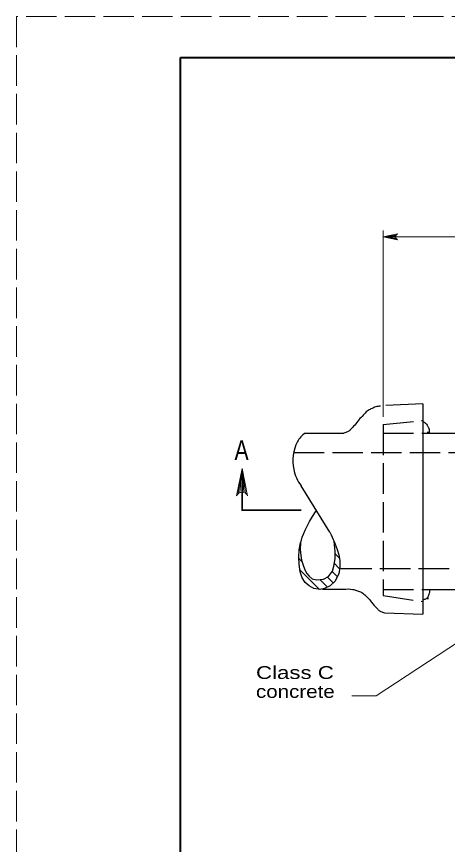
# Model space of a CAD drawing. Extents: x 1083.1 to 1117.1, y 719.4 to 741.4.
# Drawn here: x 1083.13 to 1088.38, y 731.26 to 741.35 of the extents above; entities that cross this region are included whole.
import ezdxf
from ezdxf.enums import TextEntityAlignment as Align

# ---------------------------------------------------------------- set-up
doc = ezdxf.new("R2010")
doc.units = 0
doc.header["$LTSCALE"] = 0.062
doc.linetypes.add('LONG_DASHED', pattern=[7.5, 6, -1.5])
doc.layers.add('1', color=7, linetype='Continuous', lineweight=13)

msp = doc.modelspace()

# ---------------------------------------------------------------- linework, layer by layer
at = {"layer": '1', "lineweight": 25}
for p, q in [((1085.12642, 740.85408), (1116.62642, 740.85408)), ((1088.08092, 736.63083), (1087.63217, 736.61167)), ((1088.08092, 736.63083), (1088.08092, 734.06592)), ((1086.64692, 736.27608), (1087.08667, 736.27608)), ((1087.08667, 736.27608), (1087.11675, 736.27608)), ((1088.08092, 736.27608), (1088.70717, 736.27608)), ((1086.94692, 735.0665), (1086.59733, 735.63325)), ((1086.85717, 734.37325), (1087.08667, 734.37325)), ((1087.08667, 734.37325), (1087.11675, 734.37325)), ((1088.08092, 734.36742), (1088.72042, 734.36742)), ((1087.61542, 734.08575), (1088.08092, 734.06592))]:
    msp.add_line(p, q, dxfattribs=at)
at = {"layer": '1'}
for p, q in [((1087.59625, 738.74692), (1087.59625, 736.47533)), ((1087.75742, 738.69033), (1087.59625, 738.66783)), ((1087.75192, 738.67917), (1087.59625, 738.66783)), ((1087.59625, 738.66783), (1094.52958, 738.66783)), ((1087.75025, 738.66783), (1087.59625, 738.66783)), ((1087.75317, 738.65333), (1087.59625, 738.66783)), ((1087.75933, 738.64292), (1087.59625, 738.66783)), ((1085.83083, 735.53767), (1085.87792, 735.84575)), ((1085.85058, 735.54933), (1085.87792, 735.84575)), ((1085.87792, 735.55475), (1085.87792, 735.84575)), ((1085.89942, 735.55158), (1085.87792, 735.84575)), ((1085.9205, 735.54125), (1085.87792, 735.84575)), ((1087.00217, 734.94825), (1087.0005, 734.94983)), ((1087.00825, 734.9325), (1087.00158, 734.93933)), ((1086.587, 734.85367), (1086.57717, 734.8635)), ((1086.58683, 734.85742), (1086.57775, 734.86667)), ((1086.58967, 734.90692), (1086.58617, 734.91042)), ((1086.60825, 734.707), (1086.5695, 734.74567)), ((1087.06417, 734.75092), (1087.01175, 734.8035)), ((1087.06708, 734.62242), (1087.002, 734.68775)), ((1086.8195, 734.36942), (1086.58083, 734.60892)), ((1086.98917, 734.44983), (1086.91883, 734.52042)), ((1087.03858, 734.52567), (1086.97658, 734.588)), ((1086.91725, 734.3965), (1086.82442, 734.48983))]:
    msp.add_line(p, q, dxfattribs=at)
at = {"layer": '1', "linetype": 'LONG_DASHED', "lineweight": 25}
for p, q in [((1087.59625, 736.379), (1088.08092, 736.43042)), ((1087.59625, 736.379), (1087.59625, 734.29408)), ((1087.59625, 736.27608), (1088.08092, 736.27608)), ((1086.50708, 736.03933), (1090.24283, 736.03933)), ((1087.08633, 734.62317), (1090.24283, 734.62317)), ((1087.59625, 734.36742), (1088.08092, 734.36742)), ((1087.59625, 734.29408), (1088.08092, 734.22375))]:
    msp.add_line(p, q, dxfattribs=at)
at = {"layer": '1', "linetype": 'LONG_DASHED'}
msp.add_line((1087.06867, 734.62317), (1087.08667, 734.62317), dxfattribs=at)
msp.add_lwpolyline([(1083.12642, 719.35408), (1117.12642, 719.35408), (1117.12642, 741.35408), (1083.12642, 741.35408)], close=True, dxfattribs=at)
at = {"layer": '1', "lineweight": 25}
for points in [[(1116.62642, 719.85408), (1085.12642, 719.85408), (1085.12642, 740.85408)], [(1087.00008, 734.9535), (1087.03817, 734.85558), (1087.057, 734.79183), (1087.06908, 734.72342), (1087.06867, 734.63167), (1087.05642, 734.562), (1087.01208, 734.47133), (1086.95183, 734.41475), (1086.8845, 734.37917), (1086.82967, 734.36742), (1086.75108, 734.38175), (1086.69708, 734.41192), (1086.647, 734.45317), (1086.60908, 734.51108), (1086.584, 734.58417), (1086.5715, 734.67892), (1086.569, 734.764), (1086.57475, 734.85092), (1086.5915, 734.9385)], [(1087.00008, 734.9535), (1087.03817, 734.85558), (1087.057, 734.79183), (1087.06908, 734.72342), (1087.06867, 734.63167), (1087.05642, 734.562), (1087.01208, 734.47133), (1086.95183, 734.41475), (1086.8845, 734.37917), (1086.82967, 734.36742), (1086.75108, 734.38175), (1086.69708, 734.41192), (1086.647, 734.45317), (1086.60908, 734.51108), (1086.584, 734.58417), (1086.5715, 734.67892), (1086.569, 734.764), (1086.57475, 734.85092), (1086.5915, 734.9385)], [(1086.5915, 734.9385), (1086.58675, 734.85592), (1086.594, 734.78267), (1086.60258, 734.72667), (1086.61692, 734.67625), (1086.64125, 734.60717), (1086.66842, 734.5655), (1086.69708, 734.5295), (1086.7315, 734.50075), (1086.783, 734.48633), (1086.86892, 734.4935), (1086.93067, 734.52658), (1086.97925, 734.59133), (1086.9965, 734.65325), (1087.01075, 734.741), (1087.01225, 734.83167), (1087.00008, 734.9535)], [(1086.5915, 734.9385), (1086.58675, 734.85592), (1086.594, 734.78267), (1086.60258, 734.72667), (1086.61692, 734.67625), (1086.64125, 734.60717), (1086.66842, 734.5655), (1086.69708, 734.5295), (1086.7315, 734.50075), (1086.783, 734.48633), (1086.86892, 734.4935), (1086.93067, 734.52658), (1086.97925, 734.59133), (1086.9965, 734.65325), (1087.01075, 734.741), (1087.01225, 734.83167), (1087.00008, 734.9535)]]:
    msp.add_lwpolyline(points, dxfattribs=at)
at = {"layer": '1', "lineweight": 40}
msp.add_lwpolyline([(1085.12642, 740.85408), (1116.62642, 740.85408), (1116.62642, 719.85408), (1085.12642, 719.85408)], close=True, dxfattribs=at)
msp.add_lwpolyline([(1085.12642, 740.85408), (1116.62642, 740.85408), (1116.62642, 719.85408), (1085.12642, 719.85408)], close=True, dxfattribs=at)
at = {"layer": '1'}
for points in [[(1087.77425, 738.63217), (1087.59625, 738.66783), (1087.77425, 738.70342)], [(1085.81067, 735.50942), (1085.87792, 735.84575), (1085.94517, 735.50942)], [(1088.90908, 733.98758), (1087.51283, 733.07425), (1087.2155, 733.07425)]]:
    msp.add_lwpolyline(points, dxfattribs=at)
at = {"layer": '1', "lineweight": 35}
msp.add_lwpolyline([(1086.59908, 735.33458), (1085.87792, 735.33458), (1085.87792, 735.64792)], dxfattribs=at)
at = {"layer": '1'}
msp.add_arc((1085.878, 735.48227), 0.07258, 22.08782, 157.91395, dxfattribs=at)
msp.add_ellipse((1087.78872, 738.66781), major_axis=(-0.03843, 0), ratio=0.999895, start_param=5.0978942, end_param=7.46850734, dxfattribs=at)
at = {"layer": '1', "lineweight": 25}
for centre, major_axis, start_param, end_param in [((1086.8297, 736.01254), (0, 0.32118), 0.60853498, 1.05234758), ((1087.02701, 735.93557), (0, -0.53235), 4.25283424, 4.90421148), ((1086.97645, 735.92727), (0, -0.48097), 4.9073919, 5.37012799)]:
    msp.add_ellipse(centre, major_axis=major_axis, ratio=0.995779, start_param=start_param, end_param=end_param, dxfattribs=at)
for points in [[(1087.5645, 736.604), (1087.50825, 736.59633), (1087.4495, 736.5695), (1087.40308, 736.54458), (1087.35392, 736.49217), (1087.30192, 736.43775), (1087.24775, 736.36883), (1087.207, 736.32658), (1087.17933, 736.30025), (1087.14258, 736.28367), (1087.11675, 736.27608)], [(1088.08192, 736.41408), (1088.09792, 736.40817), (1088.11192, 736.39858), (1088.12692, 736.383), (1088.14392, 736.35683), (1088.15167, 736.34192), (1088.15742, 736.31958), (1088.15983, 736.29442), (1088.16125, 736.2765)], [(1087.11675, 734.37325), (1087.22675, 734.37042), (1087.27425, 734.35808), (1087.32267, 734.33908), (1087.375, 734.302), (1087.452, 734.22025), (1087.4845, 734.1785), (1087.52525, 734.13625), (1087.55283, 734.11), (1087.58967, 734.09333), (1087.61542, 734.08575)], [(1088.08083, 734.247), (1088.09525, 734.2475), (1088.11033, 734.25092), (1088.12825, 734.25867), (1088.13842, 734.26983), (1088.15583, 734.30117), (1088.16358, 734.32642), (1088.16792, 734.36808)]]:
    msp.add_spline(points, degree=3, dxfattribs=at)
for points in [[(1086.5915, 734.9385), (1086.61117, 735.01483), (1086.65233, 735.13717), (1086.78283, 735.32725)], [(1086.94692, 735.0665), (1086.96783, 735.02483), (1086.98533, 734.98717), (1087.00008, 734.9535)]]:
    msp.add_open_spline(points, degree=3, dxfattribs=at)

# ---------------------------------------------------------------- texts
at = {"layer": '1'}
for p in [(1088.11483, 736.26867), (1088.11533, 734.24975)]:
    msp.add_text('.', height=0.156, dxfattribs=at).set_placement(p)
at = {"layer": '1', "width": 0.8}
msp.add_text('A', height=0.24, dxfattribs=at).set_placement((1085.87108, 735.94925), align=Align.CENTER)
at = {"layer": '1'}
for s, width, p in [('Class C', 1.3, (1086.047, 733.278)), ('concrete', 1.2, (1086.047, 733.04725))]:
    msp.add_text(s, height=0.156, dxfattribs=dict(at, width=width)).set_placement(p)

doc.saveas('drawing.dxf')
